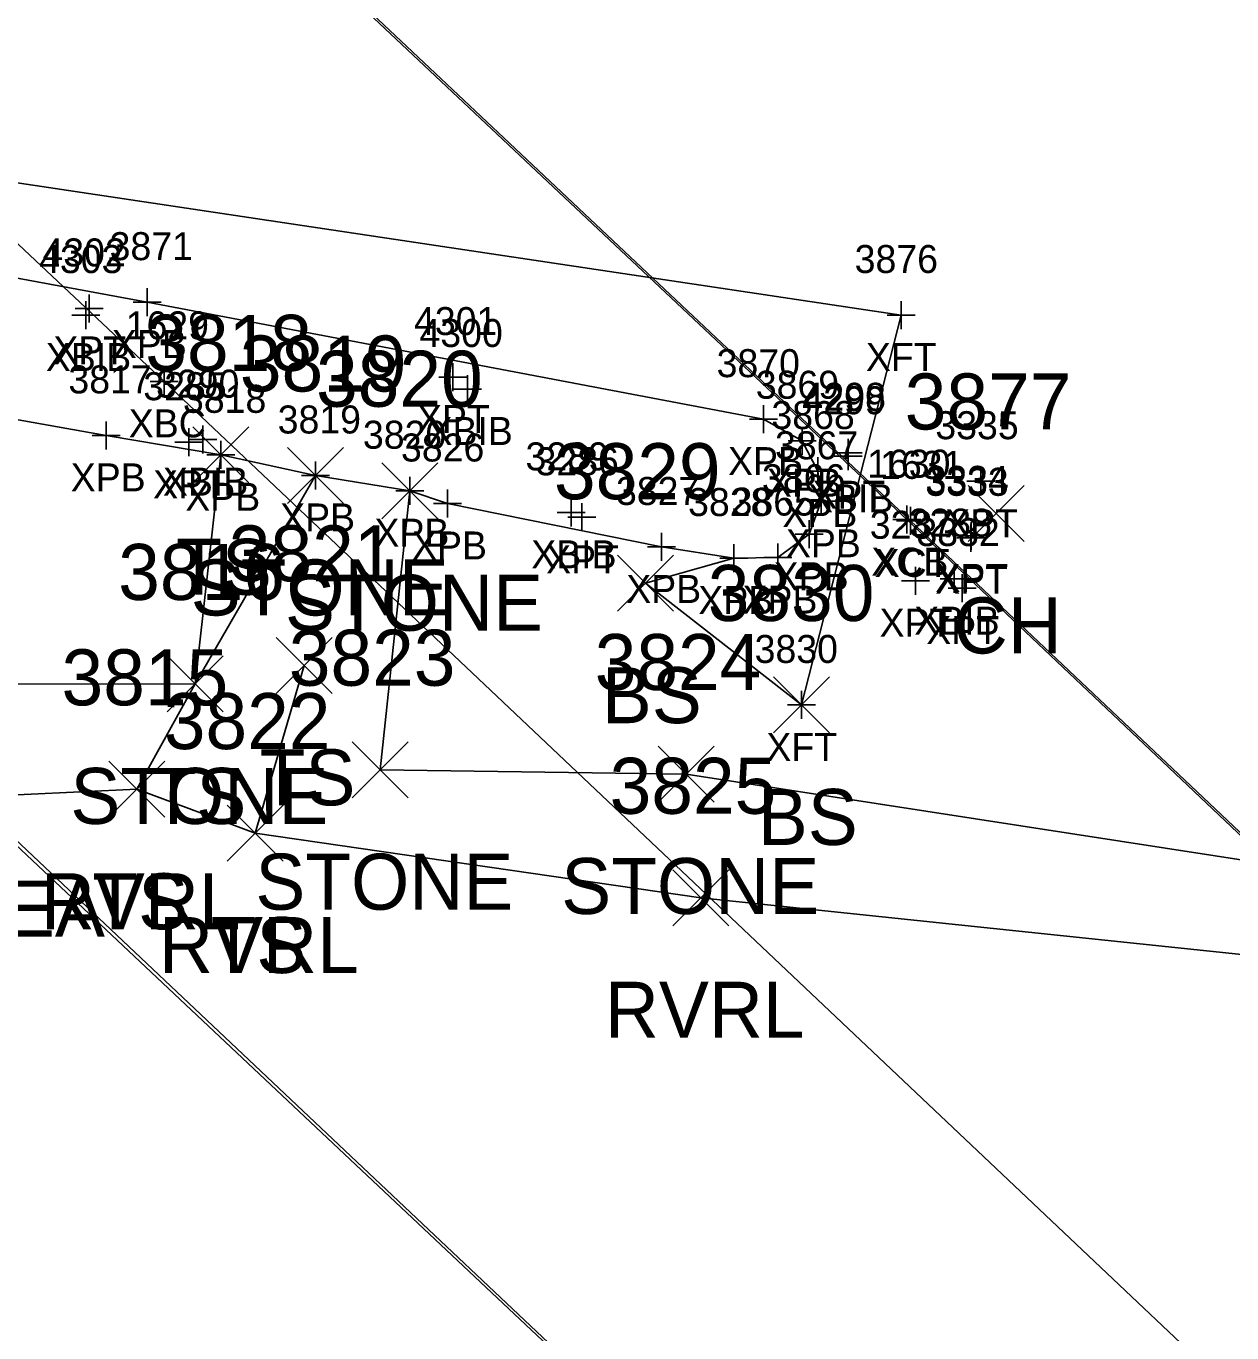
# Model space of a CAD drawing. Extents: x 1647574 to 1652703, y 212895 to 228670.
# Drawn here: x 1648991.67 to 1649034.73, y 227169.71 to 227216.38 of the extents above; entities that cross this region are included whole.
import ezdxf

# ---------------------------------------------------------------- set-up
doc = ezdxf.new("R2010")
doc.units = 0
for name, color, linetype in [('B_A', 7, 'Continuous'), ('B_I', 7, 'Continuous'), ('B_TIC', 7, 'Continuous'), ('BDC', 7, 'Continuous'), ('BELB', 7, 'Continuous'), ('BFT', 7, 'Continuous'), ('BSUBM', 7, 'Continuous'), ('L_A', 7, 'Continuous'), ('L_C', 7, 'Continuous'), ('L_I', 7, 'Continuous'), ('L_TIC', 7, 'Continuous'), ('LASF', 7, 'Continuous'), ('LAWE', 7, 'Continuous'), ('LELB', 7, 'Continuous')]:
    doc.layers.add(name, color=color, linetype=linetype)

msp = doc.modelspace()

# ---------------------------------------------------------------- linework, layer by layer
at = {"layer": 'B_TIC'}
for p, q in [((1648996.001, 227206.525), (1648996.076, 227206.525)), ((1648993.806, 227206.063), (1648993.882, 227206.063)), ((1648993.925, 227206.301), (1648994.001, 227206.301)), ((1649022.917, 227206.066), (1649022.993, 227206.066)), ((1649022.917, 227206.066), (1649022.993, 227206.066)), ((1648996.601, 227203.697), (1648996.677, 227203.697)), ((1649006.911, 227203.849), (1649006.986, 227203.849)), ((1649007.433, 227203.423), (1649007.509, 227203.423)), ((1649018.003, 227202.346), (1649018.079, 227202.346)), ((1648994.529, 227201.766), (1648994.605, 227201.766)), ((1648997.488, 227201.523), (1648997.564, 227201.523)), ((1648997.987, 227201.614), (1648998.062, 227201.614)), ((1649019.387, 227201.576), (1649019.462, 227201.576)), ((1648998.621, 227201.072), (1648998.696, 227201.072)), ((1649021.023, 227201.02), (1649021.098, 227201.02)), ((1649021.033, 227201.144), (1649021.108, 227201.144)), ((1649002.007, 227200.334), (1649002.082, 227200.334)), ((1649019.942, 227200.493), (1649020.017, 227200.493)), ((1649025.772, 227200.13), (1649025.847, 227200.13)), ((1649005.374, 227199.79), (1649005.45, 227199.79)), ((1649020.068, 227199.413), (1649020.144, 227199.413)), ((1649006.717, 227199.334), (1649006.793, 227199.334)), ((1649011.14, 227199.017), (1649011.215, 227199.017)), ((1649011.522, 227198.84), (1649011.597, 227198.84)), ((1649023.117, 227198.758), (1649023.193, 227198.758)), ((1649023.254, 227198.713), (1649023.329, 227198.713)), ((1649019.632, 227198.236), (1649019.707, 227198.236)), ((1649025.415, 227198.108), (1649025.49, 227198.108)), ((1649025.422, 227198.178), (1649025.497, 227198.178)), ((1649014.368, 227197.781), (1649014.443, 227197.781)), ((1649016.941, 227197.386), (1649017.017, 227197.386)), ((1649018.518, 227197.402), (1649018.594, 227197.402)), ((1649023.429, 227196.575), (1649023.505, 227196.575)), ((1649024.817, 227196.648), (1649024.892, 227196.648)), ((1649025.097, 227196.313), (1649025.172, 227196.313)), ((1649019.361, 227192.138), (1649019.437, 227192.138))]:
    msp.add_line(p, q, dxfattribs=at)
for points in [[(1648995.997, 227206.025), (1648995.997, 227207.025)], [(1648993.803, 227205.563), (1648993.803, 227206.563)], [(1648993.922, 227205.801), (1648993.922, 227206.801)], [(1648995.497, 227206.525), (1648996.497, 227206.525)], [(1649022.914, 227205.566), (1649022.914, 227206.566)], [(1649022.914, 227205.566), (1649022.914, 227206.566)], [(1648993.303, 227206.063), (1648994.303, 227206.063)], [(1648993.422, 227206.301), (1648994.422, 227206.301)], [(1649022.414, 227206.066), (1649023.414, 227206.066)], [(1649022.414, 227206.066), (1649023.414, 227206.066)], [(1648996.598, 227203.197), (1648996.598, 227204.197)], [(1649006.907, 227203.349), (1649006.907, 227204.349)], [(1648996.098, 227203.697), (1648997.098, 227203.697)], [(1649006.407, 227203.849), (1649007.407, 227203.849)], [(1649007.43, 227202.923), (1649007.43, 227203.923)], [(1649006.93, 227203.423), (1649007.93, 227203.423)], [(1649018, 227201.846), (1649018, 227202.846)], [(1648994.526, 227201.266), (1648994.526, 227202.266)], [(1649017.5, 227202.346), (1649018.5, 227202.346)], [(1648994.026, 227201.766), (1648995.026, 227201.766)], [(1648997.485, 227201.023), (1648997.485, 227202.023)], [(1648997.983, 227201.114), (1648997.983, 227202.114)], [(1649019.383, 227201.076), (1649019.383, 227202.076)], [(1648996.985, 227201.523), (1648997.985, 227201.523)], [(1648997.483, 227201.614), (1648998.483, 227201.614)], [(1648998.617, 227200.572), (1648998.617, 227201.572)], [(1649018.883, 227201.576), (1649019.883, 227201.576)], [(1649021.019, 227200.52), (1649021.019, 227201.52)], [(1649021.029, 227200.644), (1649021.029, 227201.644)], [(1648998.117, 227201.072), (1648999.117, 227201.072)], [(1649002.003, 227199.834), (1649002.003, 227200.835)], [(1649019.938, 227199.993), (1649019.938, 227200.993)], [(1649020.519, 227201.02), (1649021.519, 227201.02)], [(1649020.529, 227201.144), (1649021.529, 227201.144)], [(1649001.503, 227200.334), (1649002.503, 227200.334)], [(1649019.438, 227200.493), (1649020.438, 227200.493)], [(1649025.768, 227199.63), (1649025.768, 227200.63)], [(1649005.371, 227199.29), (1649005.371, 227200.29)], [(1649020.065, 227198.913), (1649020.065, 227199.913)], [(1649025.268, 227200.13), (1649026.268, 227200.13)], [(1649004.871, 227199.79), (1649005.871, 227199.79)], [(1649006.714, 227198.834), (1649006.714, 227199.834)], [(1649011.136, 227198.517), (1649011.136, 227199.517)], [(1649019.565, 227199.413), (1649020.565, 227199.413)], [(1649006.214, 227199.334), (1649007.214, 227199.334)], [(1649010.636, 227199.017), (1649011.636, 227199.017)], [(1649011.518, 227198.34), (1649011.518, 227199.34)], [(1649023.114, 227198.258), (1649023.114, 227199.258)], [(1649023.25, 227198.213), (1649023.25, 227199.213)], [(1649011.018, 227198.84), (1649012.018, 227198.84)], [(1649019.628, 227197.736), (1649019.628, 227198.736)], [(1649022.614, 227198.758), (1649023.614, 227198.758)], [(1649022.75, 227198.713), (1649023.75, 227198.713)], [(1649025.411, 227197.608), (1649025.411, 227198.608)], [(1649025.418, 227197.678), (1649025.418, 227198.678)], [(1649014.364, 227197.281), (1649014.364, 227198.281)], [(1649019.128, 227198.236), (1649020.128, 227198.236)], [(1649024.911, 227198.108), (1649025.911, 227198.108)], [(1649024.918, 227198.178), (1649025.918, 227198.178)], [(1649013.864, 227197.781), (1649014.864, 227197.781)], [(1649016.938, 227196.886), (1649016.938, 227197.886)], [(1649018.515, 227196.902), (1649018.515, 227197.902)], [(1649016.438, 227197.386), (1649017.438, 227197.386)], [(1649018.015, 227197.402), (1649019.015, 227197.402)], [(1649023.426, 227196.075), (1649023.426, 227197.075)], [(1649024.813, 227196.148), (1649024.813, 227197.148)], [(1649022.926, 227196.575), (1649023.926, 227196.575)], [(1649024.313, 227196.648), (1649025.313, 227196.648)], [(1649025.093, 227195.813), (1649025.093, 227196.813)], [(1649024.593, 227196.313), (1649025.593, 227196.313)], [(1649019.358, 227191.638), (1649019.358, 227192.638)], [(1649018.858, 227192.138), (1649019.858, 227192.138)]]:
    msp.add_lwpolyline(points, dxfattribs=at)
at = {"layer": 'BDC'}
for points in [[(1649190.777, 226999.084), (1649140.468, 227046.558), (1649090.33, 227093.733), (1649025.71, 227154.751), (1648968.186, 227208.898), (1648910.789, 227263.155), (1648860.431, 227310.794), (1648808.664, 227359.741)], [(1649190.944, 226999.114), (1649140.59, 227046.719), (1649090.397, 227093.864), (1649025.741, 227154.791), (1648968.355, 227208.988), (1648910.836, 227263.351), (1648860.59, 227310.809), (1648808.767, 227359.651)], [(1649243.4, 226991.008), (1649194.892, 227036.57), (1649144.766, 227083.811), (1649080.187, 227144.73), (1649023.114, 227198.758), (1648965.385, 227253.071), (1648915.007, 227300.535), (1648862.79, 227349.772)], [(1649243.526, 226991.095), (1649195.071, 227036.681), (1649144.945, 227083.846), (1649080.275, 227144.791), (1649023.25, 227198.713), (1648965.389, 227253.216), (1648915.176, 227300.61), (1648862.963, 227349.863)]]:
    msp.add_lwpolyline(points, dxfattribs=at)
at = {"layer": 'BELB'}
msp.add_lwpolyline([(1649218.046, 226994.506), (1649168.124, 227041.655), (1649117.675, 227088.79), (1649053.801, 227149.566), (1648996.598, 227203.697), (1648938.733, 227258.119), (1648889.571, 227305.276), (1648838.072, 227353.54)], dxfattribs=at)
at = {"layer": 'BFT'}
for points in [[(1648968.779, 227202.399), (1648971.05, 227214.981), (1648988.722, 227211.177), (1649022.914, 227206.066)], [(1649019.358, 227192.138), (1649022.914, 227206.066)]]:
    msp.add_lwpolyline(points, dxfattribs=at)
at = {"layer": 'BSUBM'}
msp.add_lwpolyline([(1648974.093, 227210.575), (1648972.651, 227210.44), (1648971.423, 227209.531), (1648971.175, 227208.007), (1648971.424, 227206.454), (1648972.551, 227205.669), (1648973.295, 227205.577), (1648985.83, 227203.305), (1648994.526, 227201.766), (1648998.617, 227201.072), (1649002.003, 227200.334), (1649005.371, 227199.79), (1649006.714, 227199.334), (1649014.364, 227197.781), (1649016.938, 227197.386), (1649018.515, 227197.402), (1649019.628, 227198.236), (1649020.065, 227199.413), (1649019.938, 227200.493), (1649019.383, 227201.576), (1649018, 227202.346), (1648995.997, 227206.525), (1648974.093, 227210.575)], dxfattribs=at)
at = {"layer": 'L_TIC'}
for points in [[(1648997.617, 227200.072), (1648999.617, 227202.072)], [(1648999.617, 227200.072), (1648997.617, 227202.072)], [(1649001.003, 227199.334), (1649003.003, 227201.334)], [(1649003.003, 227199.334), (1649001.003, 227201.334)], [(1649004.371, 227198.79), (1649006.371, 227200.79)], [(1649006.371, 227198.79), (1649004.371, 227200.79)], [(1649025.305, 227197.978), (1649027.305, 227199.978)], [(1649027.305, 227197.978), (1649025.305, 227199.978)], [(1649012.787, 227195.487), (1649014.787, 227197.487)], [(1649014.787, 227195.487), (1649012.787, 227197.487)], [(1649000.601, 227192.552), (1649002.601, 227194.552)], [(1649002.601, 227192.552), (1649000.601, 227194.552)], [(1648996.705, 227191.889), (1648998.705, 227193.889)], [(1648998.705, 227191.889), (1648996.705, 227193.889)], [(1648996.705, 227191.889), (1648998.705, 227193.889)], [(1648998.705, 227191.889), (1648996.705, 227193.889)], [(1649018.358, 227191.138), (1649020.358, 227193.138)], [(1649020.358, 227191.138), (1649018.358, 227193.138)], [(1649003.311, 227188.825), (1649005.311, 227190.825)], [(1649005.311, 227188.825), (1649003.311, 227190.825)], [(1649014.234, 227188.672), (1649016.234, 227190.672)], [(1649016.234, 227188.672), (1649014.234, 227190.672)], [(1648994.627, 227188.125), (1648996.627, 227190.125)], [(1648996.627, 227188.125), (1648994.627, 227190.125)], [(1648994.627, 227188.125), (1648996.627, 227190.125)], [(1648996.627, 227188.125), (1648994.627, 227190.125)], [(1648998.847, 227186.562), (1649000.847, 227188.562)], [(1649000.847, 227186.562), (1648998.847, 227188.562)], [(1648998.847, 227186.562), (1649000.847, 227188.562)], [(1649000.847, 227186.562), (1648998.847, 227188.562)], [(1649014.768, 227184.251), (1649016.768, 227186.251)], [(1649016.768, 227184.251), (1649014.768, 227186.251)]]:
    msp.add_lwpolyline(points, dxfattribs=at)
at = {"layer": 'LASF'}
for points in [[(1648499.797, 227390.788), (1648534.237, 227361.964), (1648564.139, 227335.998), (1648594.151, 227310.22), (1648628.599, 227293.401), (1648654.269, 227279.63), (1648686.156, 227265.624), (1648717.135, 227256.764), (1648740.627, 227248.949), (1648765.894, 227244.077), (1648814.223, 227231.854), (1648833.279, 227225.74), (1648856.547, 227221.689), (1648882.063, 227215.369), (1648909.355, 227210.97), (1648936.503, 227203.804), (1648961.566, 227198.174), (1648983.303, 227192.864), (1648997.705, 227192.889), (1649002.003, 227200.334)], [(1649005.371, 227199.79), (1649004.311, 227189.825), (1649015.234, 227189.672), (1649059.809, 227182.78), (1649089.548, 227178.729), (1649126.923, 227169.017), (1649156.272, 227163.599), (1649190.782, 227157.852), (1649212.908, 227155.758), (1649246.111, 227149.814), (1649279.77, 227142.889), (1649298.177, 227138.585), (1649312.901, 227137.94)]]:
    msp.add_lwpolyline(points, dxfattribs=at)
at = {"layer": 'LAWE'}
msp.add_lwpolyline([(1648882.174, 227213.58), (1648908.492, 227208.957), (1648937.017, 227202.591), (1648961.62, 227196.414), (1648987.564, 227188.752), (1648995.627, 227189.125), (1648999.847, 227187.562), (1649015.768, 227185.251), (1649058.819, 227180.733), (1649088.746, 227176.451), (1649126.054, 227169.003), (1649155.538, 227162.793), (1649190.065, 227156.482), (1649213.142, 227152.135), (1649245.722, 227144.443), (1649279.437, 227140.081), (1649297.816, 227135.47), (1649313.399, 227135.549)], dxfattribs=at)
at = {"layer": 'LELB'}
msp.add_line((1649001.601, 227193.552), (1649001.601, 227193.552), dxfattribs=at)
for points in [[(1648995.627, 227189.125), (1648997.705, 227192.889), (1648998.617, 227201.072)], [(1649013.787, 227196.487), (1649016.938, 227197.386)], [(1649013.787, 227196.487), (1649019.358, 227192.138)], [(1649001.601, 227193.552), (1648999.847, 227187.562)]]:
    msp.add_lwpolyline(points, dxfattribs=at)

# ---------------------------------------------------------------- texts
at = {"layer": 'B_A'}
for s, p in [('XPB', (1648994.733, 227204.525)), ('XBIB', (1648992.374, 227204.063)), ('XPT', (1648992.642, 227204.301)), ('XFT', (1649021.658, 227204.066)), ('XFT', (1649021.658, 227204.066)), ('XBC', (1648995.334, 227201.697)), ('XPT', (1649005.628, 227201.849)), ('XBIB', (1649006.001, 227201.423)), ('XPB', (1649016.736, 227200.346)), ('XPB', (1648993.262, 227199.766)), ('XPT', (1648996.205, 227199.523)), ('XBIB', (1648996.554, 227199.614)), ('XPB', (1649018.12, 227199.576)), ('XPB', (1648997.353, 227199.072)), ('XBIB', (1649019.59, 227199.02)), ('XPT', (1649019.75, 227199.144)), ('XPB', (1649018.675, 227198.493)), ('XPB', (1649000.74, 227198.334)), ('XPT', (1649024.489, 227198.13)), ('XPB', (1649004.107, 227197.79)), ('XPB', (1649005.45, 227197.334)), ('XBIB', (1649009.707, 227197.017)), ('XPB', (1649018.801, 227197.413)), ('XPT', (1649010.239, 227196.84)), ('XCB', (1649021.85, 227196.758)), ('XCT', (1649021.971, 227196.713)), ('XPB', (1649018.364, 227196.236)), ('XPT', (1649024.132, 227196.108)), ('XPT', (1649024.139, 227196.178)), ('XPB', (1649013.1, 227195.781)), ('XPB', (1649015.674, 227195.386)), ('XPB', (1649017.251, 227195.402)), ('XBIB', (1649023.384, 227194.648)), ('XPT', (1649022.146, 227194.575)), ('XPT', (1649023.814, 227194.313)), ('XFT', (1649018.102, 227190.138))]:
    msp.add_text(s, height=1, dxfattribs=at).set_placement(p)
at = {"layer": 'B_I'}
for s, p in [('4302', (1648992.252, 227207.801)), ('3871', (1648994.651, 227208.025)), ('4303', (1648992.134, 227207.563)), ('3876', (1649021.257, 227207.566)), ('3876', (1649021.257, 227207.566)), ('1629', (1648995.224, 227205.197)), ('4301', (1649005.521, 227205.349)), ('4300', (1649005.717, 227204.923)), ('3870', (1649016.327, 227203.846)), ('3817', (1648993.179, 227203.266)), ('3290', (1648996.31, 227203.114)), ('3869', (1649017.726, 227203.076)), ('3285', (1648995.855, 227203.023)), ('3818', (1648997.271, 227202.572)), ('4298', (1649019.399, 227202.644)), ('4299', (1649019.385, 227202.52)), ('3819', (1649000.653, 227201.834)), ('3868', (1649018.285, 227201.993)), ('3335', (1649024.138, 227201.63)), ('3820', (1649003.697, 227201.29)), ('3826', (1649005.056, 227200.834)), ('3867', (1649018.412, 227200.913)), ('3289', (1649009.503, 227200.517)), ('3286', (1649009.861, 227200.34)), ('1630', (1649021.701, 227200.258)), ('1631', (1649022.164, 227200.213)), ('3866', (1649017.947, 227199.736)), ('3333', (1649023.781, 227199.608)), ('3334', (1649023.788, 227199.678)), ('3827', (1649012.734, 227199.281)), ('3828', (1649015.308, 227198.886)), ('3865', (1649016.861, 227198.902)), ('3287', (1649021.796, 227198.075)), ('3288', (1649023.184, 227198.148)), ('3332', (1649023.463, 227197.813)), ('3830', (1649017.685, 227193.638))]:
    msp.add_text(s, height=1, dxfattribs=at).set_placement(p)
at = {"layer": 'L_A'}
for s, p in [('TS', (1648997.027, 227196.072)), ('STONE', (1648997.547, 227195.334)), ('STONE', (1649000.914, 227194.79)), ('CH', (1649024.793, 227193.978)), ('BS', (1649012.228, 227191.487)), ('TS', (1649000.011, 227188.552)), ('STONE', (1648993.249, 227187.889)), ('TS', (1648996.115, 227187.889)), ('BS', (1649017.799, 227187.138)), ('STONE', (1648999.855, 227184.825)), ('STONE', (1649010.778, 227184.672)), ('RVRL', (1648992.194, 227184.125)), ('TS', (1648994.037, 227184.125)), ('RVRL', (1648996.414, 227182.562)), ('TS', (1648998.257, 227182.562)), ('RVRL', (1649012.335, 227180.251))]:
    msp.add_text(s, height=2, dxfattribs=at).set_placement(p)
at = {"layer": 'L_C'}
msp.add_text('ROCK SLIDE AREA', height=2, dxfattribs=at).set_placement((1648970.256, 227183.864))
at = {"layer": 'L_I'}
for s, p in [('3818', (1648995.925, 227204.072)), ('3819', (1648999.303, 227203.334)), ('3820', (1649002.024, 227202.79)), ('3877', (1649023.045, 227201.978)), ('3829', (1649010.519, 227199.487)), ('3821', (1648998.908, 227196.552)), ('3816', (1648994.958, 227195.889)), ('3816', (1648994.958, 227195.889)), ('3830', (1649016.012, 227195.138)), ('3823', (1649001.051, 227192.825)), ('3824', (1649011.975, 227192.672)), ('3815', (1648992.935, 227192.125)), ('3815', (1648992.935, 227192.125)), ('3822', (1648996.587, 227190.562)), ('3822', (1648996.587, 227190.562)), ('3825', (1649012.508, 227188.251))]:
    msp.add_text(s, height=2, dxfattribs=at).set_placement(p)

doc.saveas('drawing.dxf')
